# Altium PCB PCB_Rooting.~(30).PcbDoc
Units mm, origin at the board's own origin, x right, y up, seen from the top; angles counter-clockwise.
Board outline 68.5 x 51 mm, 4 copper layers (Top Layer, Mid-Layer 1, Mid-Layer 2, Bottom Layer); 59 components, 42 nets, 186 pads, 43 vias.
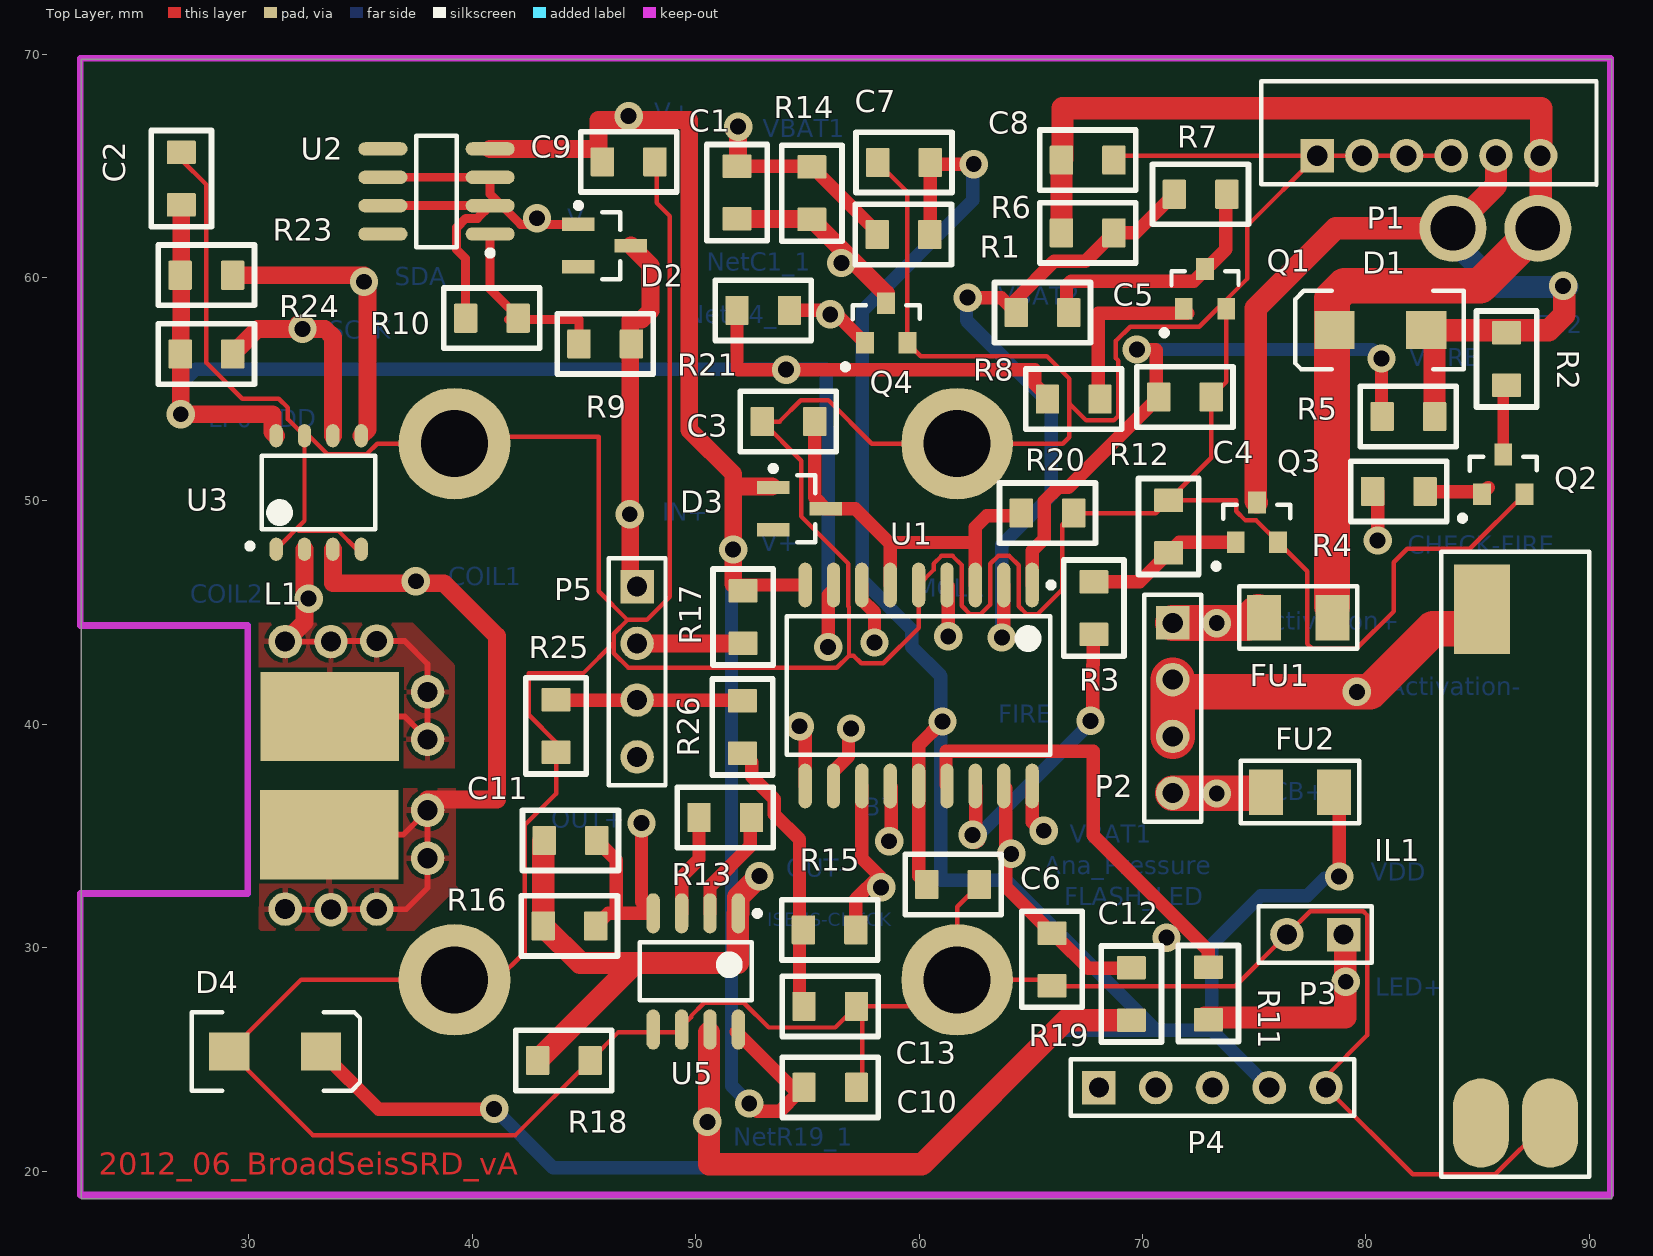
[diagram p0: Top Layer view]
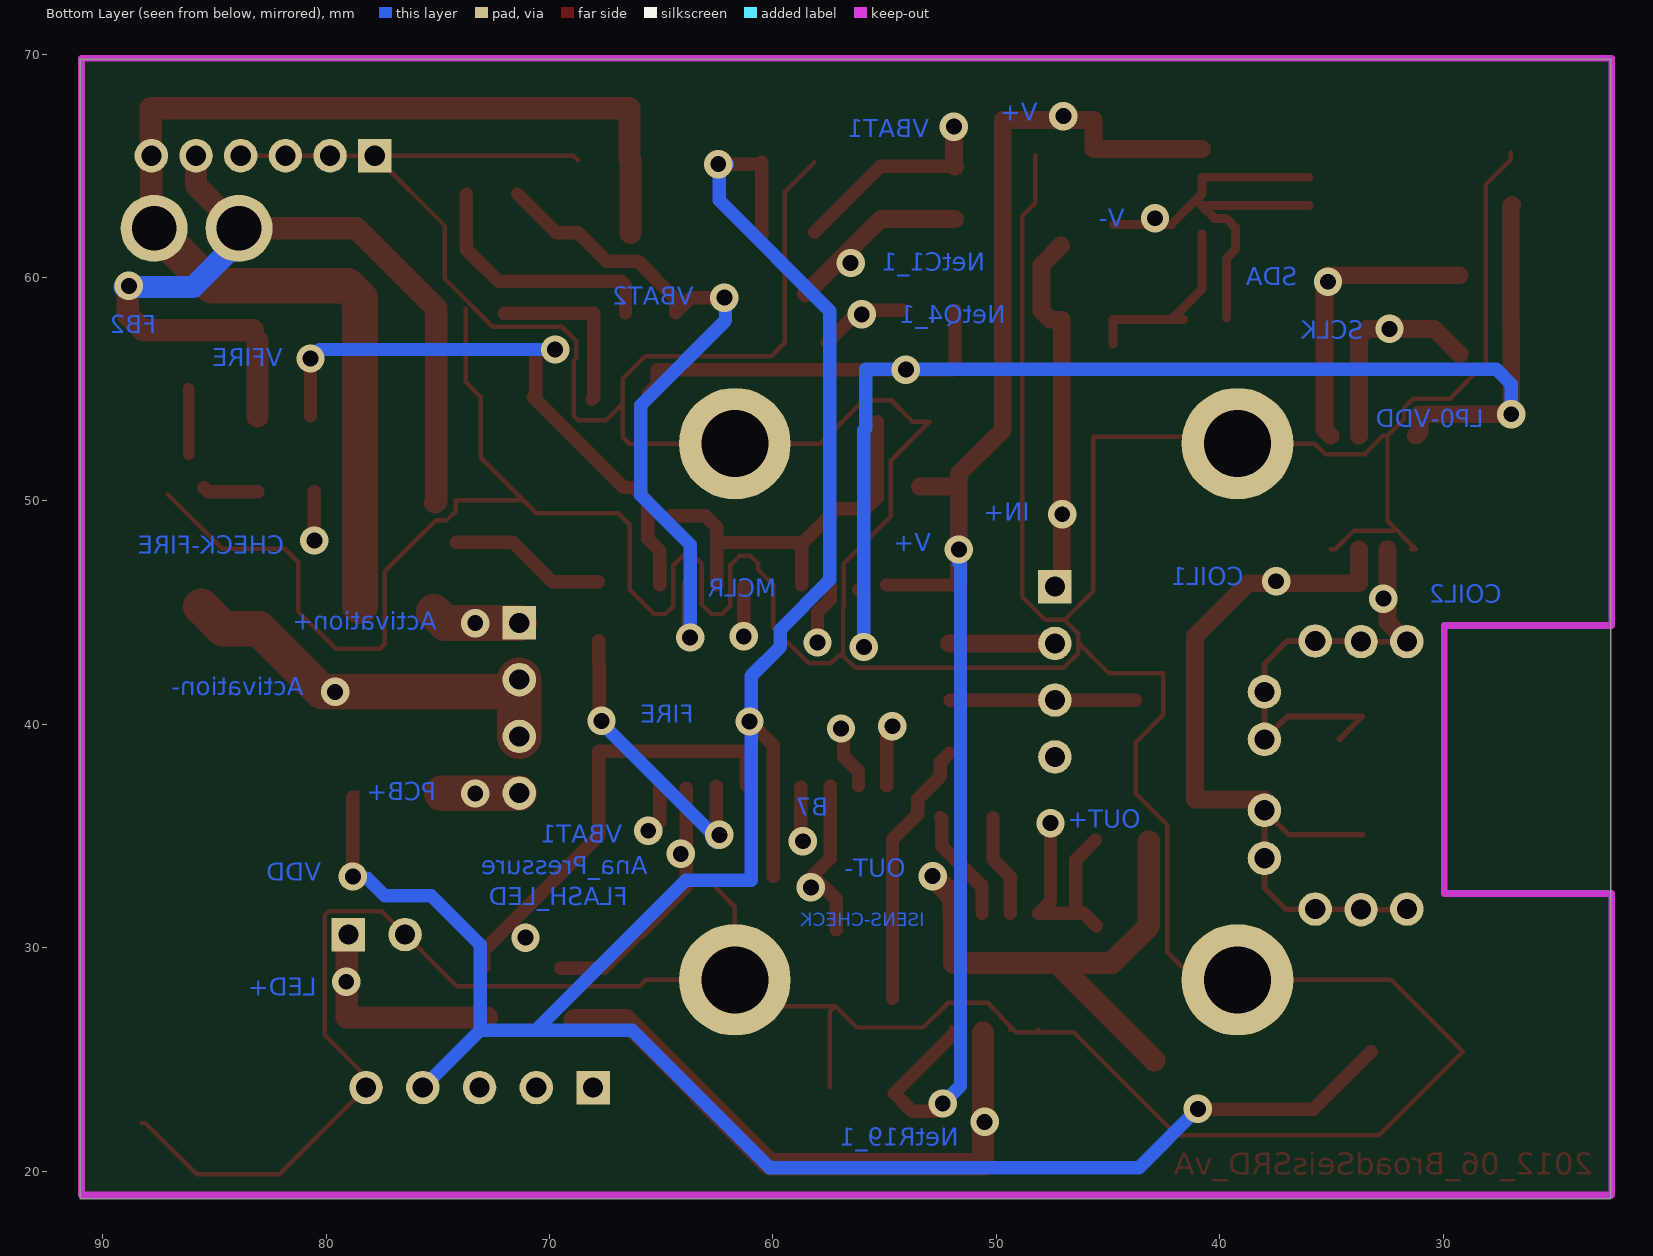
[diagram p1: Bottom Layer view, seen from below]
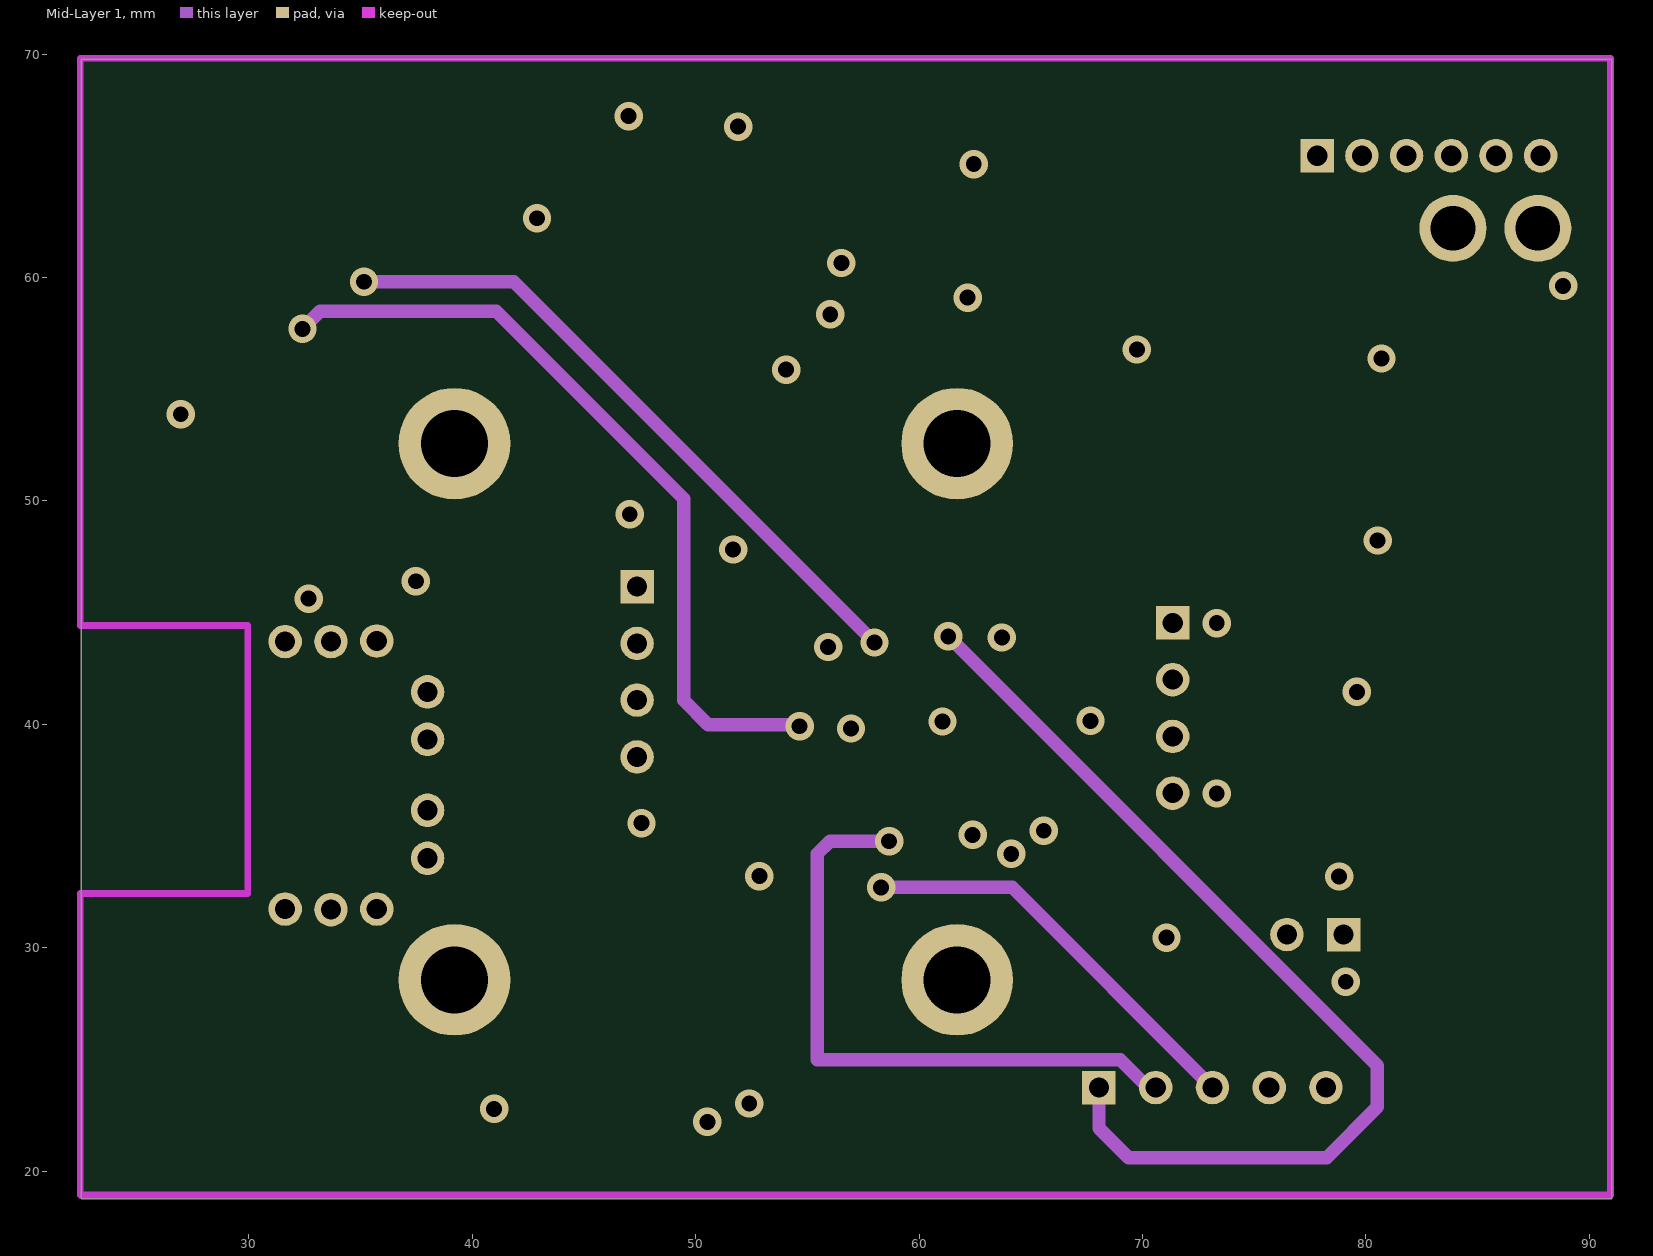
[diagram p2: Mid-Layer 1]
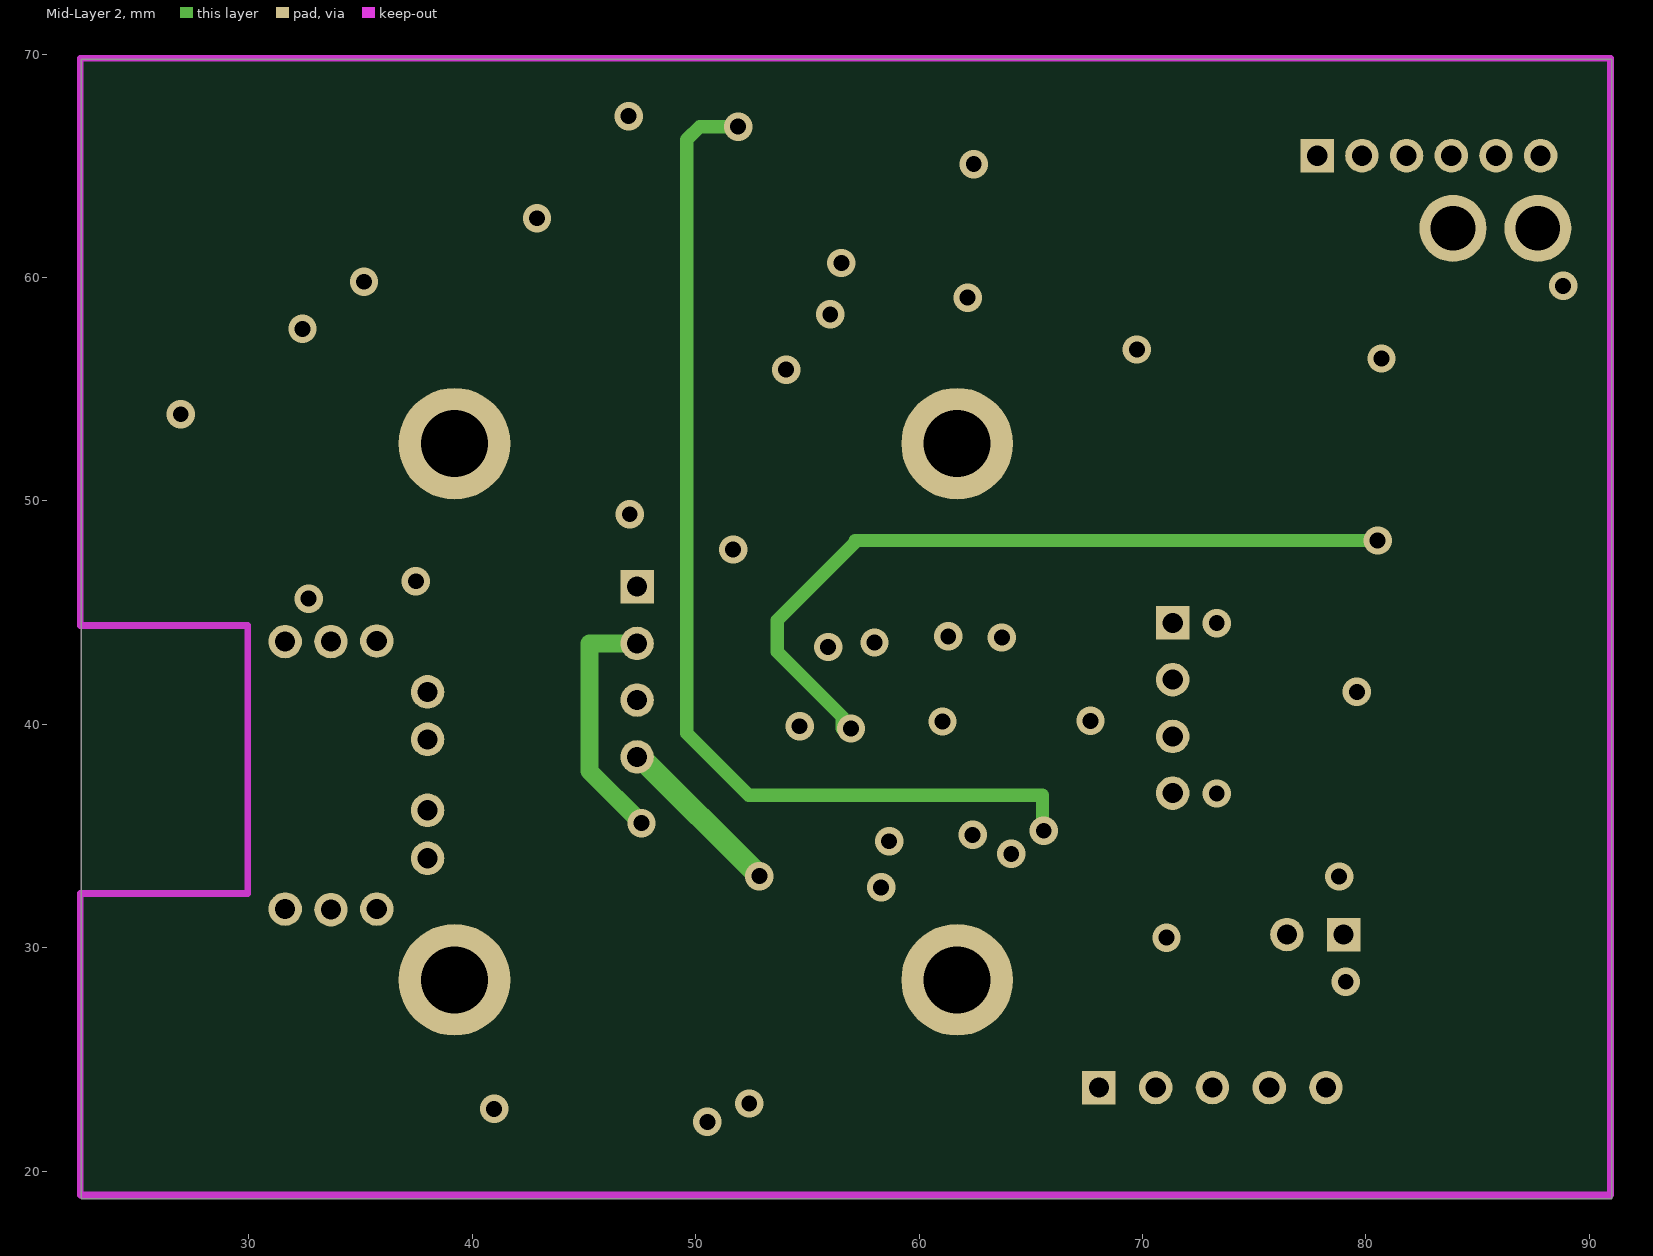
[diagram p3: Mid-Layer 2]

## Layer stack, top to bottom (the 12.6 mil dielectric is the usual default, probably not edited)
Top Layer: signal copper 0.0356
Dielectric: dielectric 0.32, FR-4, Dk 4.8
Mid-Layer 1: signal copper 0.0356
Dielectric: dielectric 0.32, FR-4, Dk 4.8
Mid-Layer 2: signal copper 0.0356
Dielectric: dielectric 0.32, FR-4, Dk 4.8
Bottom Layer: signal copper 0.0356

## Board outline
22.505,18.76 91.005,18.76 91.005,69.76 22.505,69.76

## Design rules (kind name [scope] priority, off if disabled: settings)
Clearance [All] p1: gap=0.2
HoleSize [All] p1: absolutevalues=TRUE maxlimit=5 minlimit=0.025 maxpercent=80.000 minpercent=20.000
PolygonConnect [All] p1: connectstyle=Relief reliefconductorwidth=0.254 reliefentries=4 polygonreliefangle="90 Angle"
RoomDefinition PCB_Schematics [InComponentClass('PCB_Schematics')] p1: confinementstyle=ConfineIn formatcopy=TRUE lockcomponents=FALSE outline 0,0 99.975,0 99.975,77.475 0,77.475
RoutingVias [All] p1: holewidth=0.6 width=1 viastyle="Through Hole" minholewidth=0.711 minwidth=1.27 maxholewidth=0.711 maxwidth=1.27
SilkscreenOverComponentPads [All] p1: minsilkscreentomaskgap=0.254
SolderMaskExpansion [All] p1: expansion=0.102
Width [All] p1: maxlimit=2 minlimit=0.2 preferedwidth=0.6
26 further rules are at their usual default settings.

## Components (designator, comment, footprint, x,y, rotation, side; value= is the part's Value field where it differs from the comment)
C1 "" 1608[0603] 51.85,63.8 r90 top
C2 "" 1608[0603] 26.975,64.425 r270 top
C3 "" 1608[0603] 54.15,53.55 r0 top
C4 "" 1608[0603] 71.9,54.65 r180 top
C5 "" 1608[0603] 65.525,58.425 r180 top
C6 "" 1608[0603] 61.525,32.825 r180 top
C7 "" 1608[0603] 59.325,65.15 r0 top
C8 "" 1608[0603] 67.55,65.25 r180 top
C9 "" 1608[0603] 47,65.175 r180 top
C10 "" 1608[0603] 56.025,23.75 r180 top
C11 "" 1608[0603] 44.4,34.8 r0 top
C12 "" 1608[0603] 65.95,29.475 r90 top
C13 "" 1608[0603] 56.025,27.375 r180 top
D1 "" DiodeRS1D(recommendedfootprint) 80.65,57.65 r180 top
D2 "" SOT-23_M 45.925,61.425 r0 top
D3 "" SOT-23_M 54.65,49.65 r0 top
D4 "" DiodeRS1D(recommendedfootprint) 31.175,25.35 r0 top
FU1 "1A" FU(recommendedfootprint) 76.975,44.775 r0 top
FU2 "200mA" FU(recommendedfootprint) 77.055,36.96 r180 top
IL1 "ILS" ILS 88.15,45.15 r270 top
L1 "" INDC4532 33.625,37.7 r270 top
P1 "ConnectorToFB" "HIROSE DF3A-6P" 77.825,65.45 r0 top
P2 "Battery Pack pigtail" HDR1X4 71.355,44.535 r270 top
P3 "Connector to LED" HDR1X2 79.005,30.585 r180 top
P4 "Connector to Prog." HDR1X5 68.055,23.735 r0 top
P5 "Pressure Transducer pigtail" HDR1X4 47.38,46.16 r270 top
Q1 "" transistor_SOT-23(recommendedfootprint) 72.8,59.575 r90 top
Q2 "" transistor_SOT-23(recommendedfootprint) 86.15,51.275 r90 top
Q3 "" transistor_SOT-23(recommendedfootprint) 75.125,49.125 r90 top
Q4 "" transistor_SOT-23(recommendedfootprint) 58.525,58.05 r90 top
R1 "" J1-0603 59.3,61.925 r0 top
R2 "" J1-0603 86.3,56.35 r90 top
R3 "" J1-0603 67.825,45.2 r90 top
R4 "" J1-0603 81.475,50.425 r0 top
R5 "" J1-0603 81.9,53.775 r0 top
R6 "" J1-0603 67.55,62 r180 top
R7 "" J1-0603 72.6,63.725 r180 top
R8 "" J1-0603 66.925,54.55 r0 top
R9 "" J1-0603 45.95,57.025 r0 top
R10 "" J1-0603 40.875,58.175 r180 top
R11 "" J1-0603 72.95,27.95 r90 top
R12 "" J1-0603 71.175,48.85 r270 top
R13 "" J1-0603 51.325,35.825 r0 top
R14 "" J1-0603 55.2,63.775 r90 top
R15 "" J1-0603 56,30.8 r180 top
R16 "" J1-0603 44.35,30.975 r0 top
R17 "" J1-0603 52.125,44.8 r90 top
R18 "" 1608[0603] 44.1,24.95 r180 top
R19 "" J1-0603 69.5,27.925 r90 top
R20 "" J1-0603 65.75,49.45 r180 top
R21 "" J1-0603 53.025,58.525 r0 top
R23 "" J1-0603 28.1,60.1 r0 top
R24 "" J1-0603 28.1,56.575 r180 top
R25 "" J1-0603 43.75,39.925 r90 top
R26 "" J1-0603 52.1,39.875 r90 top
U1 "PIC16LF1827-I/SO" SOIC-SO18_L 59.98,41.735 r270 top
U2 "LM334D" SO8_N 38.4,63.85 r180 top
U3 "M24LR64" SO8N_N 33.125,50.375 r90 top
U5 "AD620BR" R-8D_N 50.005,28.935 r270 top

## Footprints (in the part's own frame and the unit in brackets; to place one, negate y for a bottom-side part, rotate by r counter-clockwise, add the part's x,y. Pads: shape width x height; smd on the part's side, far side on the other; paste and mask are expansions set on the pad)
1608[0603] [mm] "Chip Capacitor, Body 1.6x0.8mm, IPC High Density"
  rrect10% 1.05x1.3 smd: 1(-1.175,0) 2(1.175,0)
  silkscreen extent -2.15,-1.35 2.15,1.35
DiodeRS1D(recommendedfootprint) [mm] "DO-214-AB/SMC; 2 C-Bend Leads; Body 7.9 x 5.9 mm, inc. leads (LxW)"
  rect 1.8x1.7 smd: 1(-2.05,0) 2(2.05,0)
  silkscreen extent -3.73,-1.75 3.8,1.75
FU(recommendedfootprint) [mm] "Thru-Hole; 2 Leads"
  rect 1.52x2.03 smd: 1(-1.525,0) 2(1.525,0)
  silkscreen extent -2.65,-1.4 2.65,1.4
HDR1X2 [mm] "Connector; Header; 2 Position"
  rect 1.5x1.5 hole 0.9: 1(0,0)
  round 1.5 hole 0.9: 2(2.54,0)
  silkscreen extent -1.27,-1.27 3.81,1.27
HDR1X4 [mm] "Connector; Header; 4 Position"
  rect 1.5x1.5 hole 0.9: 1(0,0)
  round 1.5 hole 0.9: 2(2.54,0) 3(5.08,0) 4(7.62,0)
  silkscreen extent -1.27,-1.27 8.89,1.27
HDR1X5 [mm] "Connector; Header; 5 Position"
  rect 1.5x1.5 hole 0.9: 1(0,0)
  round 1.5 hole 0.9: 2(2.54,0) 3(5.08,0) 4(7.62,0) 5(10.16,0)
  silkscreen extent -1.27,-1.27 11.43,1.27
"HIROSE DF3A-6P" [mm] "Connector; Header; 6 Position"
  rect 1.5x1.5 hole 0.9: 1(0,0)
  round 1.5 hole 0.9: 2(2,0) 3(4,0) 4(6,0) 5(8,0) 6(10,0)
  round 3 hole 2: 5(6.075,-3.25) 6(9.875,-3.25)
  Top Layer lines w0.254: 9.875,-3.25 10,-2.75
  Top Layer lines w1: 6.075,-3.25 8,-1.325 8,0 ; 10,-2.75 10,0
  silkscreen extent -2.5,-1.29 12.5,3.32
ILS [mm]
  rect 4x2.5 smd: 1(0,-2.95)
  oval 4x2.5 smd: 2(23,-3) 3(23,0.1)
  silkscreen extent -2.58,-4.77 25.4,1.85
INDC4532 [mm] "Chip Inductor, Body 4.5x3.2mm, IPC High Density"
  round 1.5 hole 0.9: 1(-6.025,2.1) 1(-6,0.05) 1(-6,-2) 1(-3.75,4.375) 1(-1.625,4.375) 2(1.55,4.375) 2(3.7,4.375) 2(5.975,2.1) 2(5.975,-2) 2(6,0.05)
  rect 4x6.2 smd: 1(-2.65,0) 2(2.65,-0.025)
  Top Layer lines w0.254: -6,-2 -6,0.05 -6.025,0.075 -6.025,2.1 -6.025,3.35 -5,4.375 -3.75,4.375 -1.625,4.375 -2.65,3.35 -2.65,0 -1.625,1.025
J1-0603 [mm] "Chip Capacitor, Body 1.6x0.8mm, IPC High Density"
  rrect10% 1.05x1.3 smd: 1(-1.175,0) 2(1.175,0)
  silkscreen extent -2.15,-1.35 2.15,1.35
R-8D_N [mm] "SOIC, 8-Leads, Body 4.9x3.9mm, Pitch 1.27mm, IPC Medium Density"
  oval 1.8x0.6 smd: 1(-2.6,1.905) 2(-2.6,0.635) 3(-2.6,-0.635) 4(-2.6,-1.905) 5(2.6,-1.905) 6(2.6,-0.635) 7(2.6,0.635) 8(2.6,1.905)
  silkscreen extent -2.72,-2.5 1.3,2.88, body extent -2,-2.5 2,2.5, height 2.59
SO8_N [mm] "SOIC, 8-Leads, Body 4.9x3.9mm, Pitch 1.27mm, IPC Medium Density"
  oval 2.2x0.6 smd: 1(-2.4,1.905) 2(-2.4,-0.635) 2(-2.4,0.635) 2(2.4,-0.635) 2(2.4,0.635) 4(-2.4,-1.905) 5(2.4,-1.905) 8(2.4,1.905)
  silkscreen extent -2.53,-2.5 0.9,2.88, body extent -1.95,-2.45 1.95,2.45, height 1.75
SO8N_N [mm] "SOP, 8-Leads, Body 5.3x5.3mm, Pitch 1.27mm, IPC Medium Density"
  oval 1.04x0.6 smd: 1(-2.54,1.905) 2(-2.54,0.635) 3(-2.54,-0.635) 4(-2.54,-1.905) 5(2.54,-1.905) 6(2.54,-0.635) 7(2.54,0.635) 8(2.54,1.905)
  silkscreen extent -2.52,-2.54 1.65,3.2, body extent -2.29,-2.54 2.29,2.54, height 2.13
SOIC-SO18_L [mm] "SOIC, 18-Leads, Body 11.5x7.5mm, Pitch 1.27mm, IPC High Density"
  oval 2x0.6 smd: 1(-4.5,5.08) 2(-4.5,3.81) 3(-4.5,2.54) 4(-4.5,1.27) 5(-4.5,0) 6(-4.5,-1.27) 7(-4.5,-2.54) 8(-4.5,-3.81) 9(-4.5,-5.08) 10(4.5,-5.08) 11(4.5,-3.81) 12(4.5,-2.54) 13(4.5,-1.27) 14(4.5,0) 15(4.5,1.27) 16(4.5,2.54) 17(4.5,3.81) 18(4.5,5.08)
  silkscreen extent -4.62,-5.9 3.1,6.06, body extent -3.8,-5.95 3.8,5.95, height 2.65
SOT-23_M [mm] "SOT23, 3-Leads, Body 2.9x1.3mm, Pitch 0.95mm, Lead Span 2.5mm, IPC Low Density"
  rect 1.45x0.6 smd: 1(-1.175,0.95) 2(-1.175,-0.95) 3(1.175,0)
  silkscreen extent -1.3,-1.5 0.7,1.92, body extent -0.7,-1.5 0.7,1.5, height 1.1
transistor_SOT-23(recommendedfootprint) [mm] "SOT23, 3-Leads, Body 2.9x1.3mm, Pitch 0.95mm, Lead Span 2.5mm, IPC Low Density"
  rect 0.972x0.802 smd: 1(-0.975,0.95) 2(-0.975,-0.95) 3(0.8,0)
  silkscreen extent -2.17,-1.5 0.7,1.95, body extent -0.7,-1.5 0.7,1.5, height 1.1

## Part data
C1 C2 C3 C4 C5 C6 C7 C8 C9 C10 C11 C12 C13: library part "Cap Semi", "Capacitor (Semiconductor SIM Model)"
D1 D4: library part Diode, "Default Diode"
D2 D3: library part "Diode BAS16", "Silicon Switching Diode for High-Speed Switching"
FU1 FU2: library part "Fuse 1", "Fuse"
IL1: "SPDT Subminiature Toggle Switch, Right Angle Mounting, Vertical Actuation"
L1: library part Inductor, "Inductor"
P1: "Header, 6-Pin"
P2 P5: "Header, 4-Pin"
P3: "Header, 2-Pin"
P4: "Header, 5-Pin"
Q1 Q2 Q4: library part NPN, "NPN Bipolar Transistor"
Q3: library part MOSFET-IRLML, "N-Channel MOSFET"
R1 R2 R3 R4 R5 R6 R7 R8 R9 R10 R11 R12 R13 R14 R15 R16 R17 R18 R19 R20 R21 R23 R24 R25 R26: library part Res3, "Resistor"
U1: "EPROM-Based 8-Bit CMOS Microcontroller, 25 Bytes RAM, 4 MHz, 18-Pin SOIC, 3.0 to 5.5V Supply Range, Extended Temperature"
U2: "Three Terminal Adjustable Current Source"
U3: "32 Kbit Serial I²C Bus EEPROM"
U5: "Low-Cost, Low-Power Instrumentation Amplifier"

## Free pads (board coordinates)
  round 5 hole 3: 1(39.205,28.56) 1(39.205,52.56) 1(61.705,28.56) 1(61.705,52.56)

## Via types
v1: diameter 1.27, hole 0.711, Top Layer to Bottom Layer, 43 vias

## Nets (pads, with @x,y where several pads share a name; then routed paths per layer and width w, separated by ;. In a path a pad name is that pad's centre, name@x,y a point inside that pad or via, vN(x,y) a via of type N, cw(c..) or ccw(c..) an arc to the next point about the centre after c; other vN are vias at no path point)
ACTIVATION+: FU1.1 P2.1 | length 4
  Top Layer w1.6: P2.1 74.68,44.535 FU1.1@75.185,45.04
  other v1: 73.325,44.525
ACTIVATION-: IL1.1 P2.2 P2.3 | length 18.6
  Top Layer w0.2: P2.2 71.89,41.46
  Top Layer w1.6: 71.89,41.46 80.185,41.46 83.005,44.28 84.605,44.28 IL1.1@85.6,45.275
  Top Layer w2: P2.3 P2.2
  other v1: 79.6,41.45
ADJ: R9.1 R10.1 U2.1 | length 8.5
  Top Layer w0.4: U2.1 40.8,59.475 42.05,58.225 R10.1 ; R10.1@41.63,58.11 44.775,58.11 R9.1
ANA_PRESSURE: C12.2 R19.2 U1.17 | length 11.4
  Top Layer w0.2: U1.17 U1.17@63.88,37.145 ; v1@63.88,33.66 v1@63.905,33.685
  Top Layer w0.6: U1.17@63.88,37.145 63.88,33.66 63.88,32.72 C12.2 ; C12.2@66.2,30.45 67.575,29.075 R19.2@69.5,29.075
  other v1: 64.125,34.2
B7: P4.2 U1.13 | length 30.8
  Top Layer w0.2: U1.13 U1.13@58.755,37.19
  Top Layer w0.6: v1(58.659,34.764) 58.659,35.014 58.755,35.11 U1.13@58.755,37.19
  Mid-Layer 1 w0.6: v1(58.659,34.764) 56.014,34.764 55.45,34.2 55.45,24.985 69.012,24.985 70.262,23.735 P4.2
CHECK-FIRE: R4.1 U1.11 | length 39.5
  Top Layer w0.2: v1@56.84,39.695 v1(56.955,39.81)
  Top Layer w0.6: U1.11 56.17,37.9 56.84,38.57 v1@56.84,39.695 ; v1(80.525,48.225) R4.1@80.525,50.4
  Mid-Layer 2 w0.6: v1@56.565,39.81 56.565,40.335 53.65,43.25 53.65,44.65 57.15,48.15 57.15,48.225 v1(80.525,48.225)
COIL1: L1.2 U3.3 | length 35.4
  Top Layer w0.254: L1.2@31.65,31.7 L1.2@33.675,31.7 ; L1.2@33.6,35.05 36.9,35.05 38,36.15 38,34 38,32.675 37.05,31.725 35.725,31.725 L1.2@33.7,31.725
  Top Layer w0.6: L1.2@31.625,31.725 L1.2@31.65,31.7 ; L1.2@33.675,31.7 L1.2@33.7,31.725
  Top Layer w0.8: U3.3 33.76,46.31 38.735,46.31 41.1,43.945 41.1,36.625 L1.2@38,36.625
  other v1: 37.475,46.4
COIL2: L1.1 U3.2 | length 4.5
  Top Layer w0.8: L1.1@31.625,43.7 32.49,44.565 U3.2
  other v1: 32.675,45.625
FB1: C8.2 D1.2 FU1.2 P1.6 R6.2 | length 53.5
  Top Layer w1: R6.2 C8.2 66.425,65.3 66.425,67.575 87.85,67.575 87.85,65.475 P1.6@87.825,65.45
  Top Layer w1.6: FU1.2@78.48,45.285 78.48,59.06 79.045,59.625 85.125,59.625 P1.6@87.7,62.2
FB2: D1.1 P1.5 Q3.3 R2.2 R5.2 | length 36.2
  Top Layer w1: Q3.3 75.075,49.975 75.075,58.625 78.65,62.2 P1.5@83.9,62.2 ; R5.2 D1.1@83.075,57.15 ; D1.1@83.275,57.635 88.185,57.635 88.875,58.325 v1@88.875,59.65
  Bottom Layer w1: P1.5@83.9,62.2 83.9,61.625 85.95,59.575 v1@89.022,59.575
  other v1: 88.832,59.625
FIRE: R3.1 U1.16 | length 14.5
  Top Layer w0.2: U1.16 U1.16@62.53,37.225
  Top Layer w0.6: v1(62.4,35.05) 62.49,35.05 62.58,34.96 62.58,34.86 62.655,34.785 62.605,34.785 62.53,34.71 U1.16@62.53,37.225 ; v1(67.675,40.15) 67.775,40.25 67.775,42.65 67.805,42.68 R3.1@67.805,43.75
  Bottom Layer w0.6: v1(62.4,35.05) 62.49,35.05 62.58,34.96 v1@67.775,40.155 ; v1@62.53,34.71 62.605,34.785 v1@62.655,34.785
FLASH_LED: R11.2 U1.15 | length 20
  Top Layer w0.2: U1.15@61.205,37.28 U1.15
  Top Layer w0.6: U1.15@61.205,37.28 61.205,38.785 67.805,38.785 67.805,35.02 72.95,29.875 R11.2
  other v1: 71.075,30.45
GND: C2.1 C3.1 C4.1 C6.1 C7.1 C8.1 C9.1 C10.1 C12.1 C13.1 D4.1 IL1.3 P1.1 P1.2 P1.3 P1.4 P3.2 P4.5 pad.1 Q1.2 Q2.2 Q3.2 Q4.2 R12.1 R18.1 R20.1 R25.1 U1.5 U3.1 U3.4 U3.7 U5.5 U5.6 | length 349.3
  Top Layer w0.2: C2.1 26.975,65.275 28.1,64.15 28.1,56.181 29.706,54.575 31.34,54.575 31.75,54.165 31.75,53.655 U3.7 ; U3.1@31.421,47.835 U3.1 32.49,49.105 U3.7 ; 32.241,48.655 34.009,48.655 34.829,47.835 U3.4 ; pad.1@38.08,54.26 39.48,52.86 45.665,52.86 45.665,45.95 46.945,44.67 ; pad.1@38.79,26.913 pad.1@38.79,27.87 ; pad.1@39.205,28.56 32.335,28.56 D4.1 32.865,21.61 41.935,21.61 R18.1 46.545,26.22 U5.5@48.215,26.22 ; pad.1@39.205,52.56 35.744,52.56 35.279,52.095 33.511,52.095 32.691,52.915 U3.7 ; pad.1@39.48,28.56 pad.1@40.45,29.53 ; pad.1@41.11,28.56 42.35,29.8 42.35,35.494 43.75,36.894 R25.1 43.75,39.2 42.525,40.425 42.525,42.275 44.955,42.275 46.33,43.65 ; U5.5 U5.5@48.215,26.22 ; C9.1@48.25,65.475 48.25,63.339 48.85,62.739 48.85,45.706 47.814,44.67 46.945,44.67 ; U5.6 U5.6@49.305,26.4 ; C10.1@57.45,23.75 57.45,27.125 C13.1 ; C7.1 59.475,63.825 Q4.2 60.075,56.475 65.725,56.475 66.725,55.475 66.725,52.85 66.435,52.56 pad.1@61.705,52.56 ; pad.1@60.52,27.375 C13.1 ; pad.1@61.705,53.855 pad.1@61.705,52.56 ; C6.1 61.705,31.83 61.705,28.56 65.69,28.56 C12.1 65.975,28.275 74.155,28.275 P3.2 ; 66.766,54.316 67.481,53.6 68.719,53.6 68.925,53.806 68.925,56.278 68.815,56.388 68.815,57.162 69.453,57.8 72.549,57.8 74.7,59.951 74.7,62.325 P1.1 ; C8.1 68.925,65.45 P1.1 ; Q1.2 73.75,55.325 C4.1 73.075,51.925 R12.1 ; P3.2@77.081,30.585 P3.2 ; P1.4 P1.3 P1.2 P1.1 ; Q2.2 84.65,47.85 81.85,47.85 81.25,47.25 81.25,45.05 79.575,43.375 77.6,43.375 77.38,43.595 77.38,46.845 Q3.2 75.1,49.125 74.614,49.125 74.2,49.539 74.2,50.025 R12.1 ; IL1.3 88.092,22.15 85.792,19.85 82.1,19.85 P4.5 78.215,24.235 80.055,26.075 80.055,31.459 79.879,31.635 77.515,31.635 P3.2 ; 46.33,43.65 46.33,43.185 46.99,42.525 56.317,42.525 56.865,43.073 ; 46.33,43.65 46.33,44.055 46.945,44.67 ; U5.5@48.215,26.22 49.125,26.22 U5.6@49.305,26.4 ; U5.6@49.305,26.4 49.796,26.891 49.796,26.939 50.391,27.535 52.159,27.535 53.269,26.425 56.25,26.425 C13.1 ; 56.865,43.073 56.865,45.261 56.84,45.286 56.84,47.186 54.725,49.301 54.725,51.8 C3.1 53.756,53.55 54.706,54.5 55.944,54.5 57.884,52.56 pad.1@61.705,52.56 ; 56.865,43.073 57.07,43.073 57.418,42.725 58.392,42.725 59.98,44.313 U1.5 60.65,46.905 60.65,47.184 61.001,47.535 61.499,47.535 61.905,47.129 61.905,45.301 62.271,44.935 62.769,44.935 63.19,45.356 63.19,47.184 63.541,47.535 64.039,47.535 64.46,47.114 64.46,45.286 64.811,44.935 65.309,44.935 66.405,46.031 66.405,48.93 R20.1 70.6,49.45 R12.1
IN+: D2.3 P5.1 R9.2 | length 16.4
  Top Layer w0.8: D2.3 47.98,60.545 47.98,58.51 47.58,58.11 47.075,58.11 47.075,46.465 P5.1
  other v1: 47.05,49.4
IN-: P5.3 R25.2 R26.2 | length 8.3
  Top Layer w0.6: R25.2@43.77,41.08 P5.3 R26.2@52.07,41.08
ISENS_CHECK: P4.3 R15.1 U1.12 | length 25.7
  Top Layer w0.6: R15.1 57.175,32.175 58.225,33.225 57.44,34.01 U1.12
  Mid-Layer 1 w0.6: v1(58.3,32.7) 64.17,32.7 P4.3
LED+: P3.1 R11.1 | length 10
  Top Layer w1: R11.1@72.8,26.875 79.08,26.875 79.08,30.51 P3.1
  other v1: 79.1,28.475
LP0-VDD: C2.2 R8.1 R21.1 R23.1 R24.2 U1.8 U3.8 | length 77.5
  Top Layer w0.2: U1.8@56.17,46.025 U1.8
  Top Layer w0.6: R21.1 51.85,55.925 51.9,55.875 v1(54.05,55.875) 65.175,55.875 65.175,55.225 R8.1@65.575,54.825 ; v1(55.93,43.46) 55.93,45.785 U1.8@56.17,46.025
  Top Layer w0.8: C2.2@26.925,63.25 26.975,63.2 26.975,57.925 ; 26.95,57.9 v1(26.95,53.875) 31.05,53.875 31.05,53.085 U3.8
  Bottom Layer w0.6: v1(26.95,53.875) 26.95,55.225 27.61,55.885 55.84,55.885 55.84,53.245 55.93,53.155 v1(55.93,43.46)
MCLR/: P4.1 U1.4 | length 47.1
  Top Layer w0.2: U1.4 U1.4@61.305,46.18
  Top Layer w0.6: v1(61.305,43.935) U1.4@61.305,46.18
  Mid-Layer 1 w0.6: v1(61.305,43.935) 80.515,24.725 80.515,22.865 78.25,20.6 69.375,20.6 68.055,21.92 P4.1
NetC1_1: C1.1 Q4.3 R14.1 | length 8.1
  Top Layer w0.8: C1.1 55.175,62.625 R14.1 Q4.3@58.525,59.275
  other v1: 56.525,60.65
NetC3_2: C3.2 D3.3 R20.2 U1.3 U1.6 | length 18.1
  Top Layer w0.6: C3.2 55.325,50.15 D3.3 57.145,49.65 58.71,48.085 ; U1.6 58.71,48.085 ; 62.445,48.135 58.76,48.135 58.71,48.085 ; U1.3 62.52,48.825 63.03,49.335 R20.2@64.575,49.335
NetC5_1: C5.1 Q1.3 R7.1 | length 11.5
  Top Layer w0.6: C5.1@66.6,58.425 66.6,59.625 66.8,59.825 72.3,59.825 73.725,61.25 R7.1@73.725,63.725
NetC13_2: C13.2 R15.2 R26.1 | length 12
  Top Layer w0.6: R26.1 52.502,38.298 52.502,37.674 53.525,36.651 53.525,35.975 54.65,34.85 C13.2@54.65,27.725
NetQ1_1: Q1.1 R8.2 | length 7.9
  Top Layer w0.6: R8.2 68.025,54.625 68.025,58.4 Q1.1@72.025,58.4
NetQ2_1: Q2.1 R4.2 | length 2.5
  Top Layer w0.6: R4.2@83.05,50.4 85.275,50.4 Q2.1@85.475,50.6
NetQ2_3: Q2.3 R2.1 | length 3.2
  Top Layer w0.2: Q2.3 Q2.3@86.3,52.225
  Top Layer w0.5: Q2.3 R2.1@86.15,55.025
NetQ3_1: Q3.1 R3.2 R12.2 | length 7.1
  Top Layer w0.6: R3.2 69.875,46.375 R12.2 71.65,48.15 Q3.1
NetQ4_1: Q4.1 R21.2 | length 4
  Top Layer w0.6: R21.2 56.125,58.525 Q4.1
  other v1: 56.025,58.35
NetR13_1: R13.1 U5.3 | length 4.6
  Top Layer w0.6: U5.3 49.37,33.13 49.35,33.15 50.15,33.95 R13.1
NetR13_2: R13.2 U5.2 | length 5.1
  Top Layer w0.6: U5.2 50.64,32.74 52.45,34.55 52.45,35.775 R13.2
NetR19_1: R19.1 U5.7 | length 26.9
  Top Layer w1: U5.7@50.596,26.201 50.596,20.3 60.125,20.3 66.575,26.75 R19.1@68.875,26.75
  other v1: 50.525,22.2
OUT+: C11.2 P5.2 R16.2 R17.1 U5.4 | length 26.6
  Top Layer w0.6: R16.2 46.085,31.535 46.45,31.535 ; C11.2 46.45,33.925 46.45,31.535 ; v1(47.575,35.575) 47.575,32.06 U5.4 46.45,31.535
  Top Layer w0.8: P5.2 52.12,43.62 R17.1
  Mid-Layer 2 w0.8: P5.2 45.24,43.62 45.24,37.91 v1(47.575,35.575)
OUT-: C11.1 P5.4 R16.1 R18.2 U5.1 | length 31.3
  Top Layer w1: R18.2 47.285,29.31 ; C11.1@43.175,34.75 R16.1 44.84,29.31 47.285,29.31 ; U5.1@51.88,31.505 51.88,29.31 47.285,29.31 ; U5.1 51.91,32.26 v1(52.85,33.2)
  Mid-Layer 2 w1: P5.4 47.51,38.54 v1(52.85,33.2)
PCB+: FU2.2 P2.4 | length 3.5
  Top Layer w1.6: P2.4 FU2.2@74.825,36.915
  other v1: 73.325,36.9
SCLK: R24.1 U1.10 U3.6 | length 48.5
  Top Layer w0.6: v1(54.655,39.91) 54.9,39.665 U1.10
  Top Layer w0.8: R24.1 30.4,57.7 v1(32.4,57.7) ; v1@32.2,57.9 v1(32.4,57.7) ; U3.6 33.76,57.335 33.395,57.7 v1(32.4,57.7)
  Mid-Layer 1 w0.6: v1(32.4,57.7) 33.185,58.485 41.08,58.485 49.475,50.09 49.475,44.55 49.472,44.547 ; 49.472,44.753 49.472,44.547 ; v1@54.855,39.985 50.555,39.985 49.472,41.068 49.472,44.547
SDA: R23.2 U1.7 U3.5 | length 45.2
  Top Layer w0.6: U1.7 57.44,45.575 58.005,45.01 v1(58.005,43.66)
  Top Layer w0.8: R23.2 35.165,60.1 35.305,59.96 35.305,53.19 U3.5
  Mid-Layer 1 w0.6: v1(35.155,59.81) 41.855,59.81 v1@57.755,43.91
V+: C9.2 C10.2 D3.1 R17.2 U1.9 U2.4 U5.8 | length 70.7
  Top Layer w0.2: R17.2@51.68,46.285 R17.2@51.73,46.235 ; U5.8@51.812,26.238 U5.8 U5.8@52.025,26.45 ; v1(52.4,23.025) v1@52.75,22.675
  Top Layer w0.6: R17.2@51.73,46.235 U1.9 ; U5.8@51.812,26.238 54.575,23.475 53.775,22.675 v1@52.75,22.675
  Top Layer w0.8: U2.4 45.655,65.755 45.655,67.05 49.715,67.05 49.715,53.175 51.68,51.21 51.68,50.65 ; R17.2@51.68,46.285 v1(51.68,47.825) 51.68,50.65 ; D3.1@53.425,50.65 51.68,50.65
  Bottom Layer w0.6: v1(51.68,47.825) 51.68,47.23 51.65,47.2 51.65,48.115 51.605,48.16 51.605,23.82 v1(52.4,23.025)
  other v1: 47,67.225
V-: D2.1 R10.2 U2.2 | length 21
  Top Layer w0.4: U2.2@36,63.215 40.8,63.215 40.23,62.645 39.71,62.645 39.3,62.235 39.3,61.245 39.7,60.845 R10.2 ; U2.2@36,64.485 40.8,64.485 40.8,63.735 42.16,62.375 D2.1
  other v1: 42.9,62.65
VBAT1: C1.2 R1.1 R14.2 U1.18 | length 59
  Top Layer w0.6: C1.2 55.175,64.975 R14.2 R1.1@58.125,62.025 ; U1.18 65.06,35.605 v1@65.28,35.385
  Top Layer w0.8: C1.2 51.9,65.025 v1(51.9,66.75)
  Mid-Layer 2 w0.6: v1(51.9,66.75) 50.175,66.75 49.6,66.175 49.6,39.6 52.375,36.825 65.525,36.825 65.525,35.29 v1(65.58,35.235)
VBAT2: C5.2 R6.1 R7.2 U1.2 | length 32.3
  Top Layer w0.6: v1@62.1,59.175 v1(62.175,59.1) 63.675,59.1 C5.2 64.35,59.031 66.044,60.725 67.45,60.725 R6.1 69.7,62 R7.2 ; v1(63.705,43.885) 63.79,43.97 U1.2
  Bottom Layer w0.6: v1@62.125,59.1 62.125,58.075 65.925,54.275 65.925,50.25 63.705,48.03 v1(63.705,43.885)
VDD: C6.2 C7.2 D4.2 FU2.1 P4.4 R1.2 U1.14 | length 123.1
  Top Layer w0.2: v1@40.955,22.76 v1(40.98,22.785) ; U1.14 U1.14@60.08,37.135 ; FU2.1 FU2.1@78.805,36.735
  Top Layer w0.6: D4.2 35.815,22.76 v1@40.955,22.76 ; C6.2@59.98,33.195 U1.14 59.98,39.055 v1(61.05,40.125) ; R1.2 60.5,61.95 C7.2 60.575,65.075 v1(62.45,65.075) ; v1(78.805,33.185) FU2.1@78.805,36.735
  Bottom Layer w0.6: v1(40.98,22.785) 43.615,20.15 60.145,20.15 66.305,26.31 70.625,26.31 ; v1@62.045,65.075 62.4,64.72 62.4,63.45 57.45,58.5 57.45,46.468 59.68,44.238 59.68,43.46 60.98,42.16 60.98,33.025 63.91,33.025 70.625,26.31 ; P4.4 73.1,26.31 ; 78.155,33.11 77.37,32.325 75.3,32.325 73.1,30.125 73.1,26.31 ; 70.625,26.31 73.1,26.31
VFIRE: C4.2 R5.1 U1.1 | length 27.7
  Top Layer w0.6: U1.1 65.06,47.76 65.6,48.3 65.6,49.976 66.224,50.6 66.675,50.6 C4.2 70.625,54.75 70.625,56.75 70.6,56.775 v1(69.75,56.775) ; R5.1@80.7,53.8 v1(80.7,56.375)
  Bottom Layer w0.6: v1(69.75,56.775) 80.3,56.775 v1(80.7,56.375)
pads on no net: D2.2 D3.2 IL1.2 U2.5 U2.8

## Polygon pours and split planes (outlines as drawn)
COIL2 on Top Layer "Top Layer-No Net" (solid, pour order 10): 30.45,44.575 30.475,44.55 37.05,44.55 37.325,44.55 39.125,42.75 39.225,42.65 39.225,38.025 30.6,38.025 30.45,38.175
COIL1 on Top Layer "Top Layer-No Net" (solid, pour order 7): 30.45,30.8 30.5,30.75 37.1,30.75 37.4,30.75 39.35,32.7 39.25,32.8 39.25,37.125 30.525,37.125

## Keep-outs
Keep-Out Layer:
  lines w0.3: 22.455,18.925 22.455,32.425 29.955,32.425 29.955,39.66 29.955,44.425 22.455,44.425 22.455,51.397 22.455,52.422 22.455,60.36 22.455,69.81 90.955,69.81 90.955,18.925 22.455,18.925

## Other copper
Top Layer:
  text "2012_06_BroadSeisSRD_vA" at 23.275,19.825 h1
Bottom Layer:
  text "V+" at 48.15,67.025 h0.8
  text "VBAT1" at 53,66.275 h0.8
  text "V-" at 44.25,62.275 h0.8
  text "NetC1_1" at 50.5,60.3 h0.8
  text "SDA" at 36.525,59.65 h0.8
  text "VBAT2" at 63.55,58.775 h0.8
  text "NetQ4_1" at 49.575,57.95 h0.8
  text "FB2" at 87.6,57.5 h0.8
  text "SCLK" at 33.575,57.25 h0.8
  text "VFIRE" at 81.95,56.025 h0.8
  text "LP0-VDD" at 28.175,53.3 h0.8
  text "IN+" at 48.5,49.1 h0.8
  text "V+" at 52.925,47.75 h0.8
  text "CHECK-FIRE" at 81.875,47.625 h0.8
  text "COIL1" at 38.925,46.225 h0.8
  text "MCLR" at 59.85,45.7 h0.8
  text "COIL2" at 27.375,45.45 h0.8
  text "Activation+" at 75.05,44.225 h0.8
  text "Activation-" at 81,41.3 h0.8
  text "FIRE" at 63.55,40.075 h0.8
  text "PCB+" at 75.075,36.6 h0.8
  text "B7" at 57.525,35.9 h0.8
  text "OUT+" at 43.525,35.375 h0.8
  text "VBAT1" at 66.75,34.7 h0.8
  text "Ana_Pressure" at 65.6,33.275 h0.8
  text "OUT-" at 54.05,33.175 h0.8
  text "VDD" at 80.225,33 h0.8
  text "FLASH_LED" at 66.5,31.9 h0.8
  text "ISENS-CHECK" at 53.2,30.95 h0.6
  text "LED+" at 80.425,27.85 h0.8
  text "NetR19_1" at 51.675,21.125 h0.8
